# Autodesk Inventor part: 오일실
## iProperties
IsCustomPart: 1
Created: 2009-02
Part Number: 오일실
Material: 고무
Description: 오일-실
Document SubType Name: Modeling
Standard: KS B 2804
Designer: SeoGD™[esajin.kr]
Standards Organization: KS
Language: ko-KR
Size Designation: S - 25 38 8
Categories: <MemberInstance><Categories><Category DisplayName="샤프트 부품" InternalName="7f7aeb1f-a693-4053-b835-cee3144e0d98" Mnemonic="SHFT"><Category DisplayName="실링" Intern
Density: 0.93 g/cm^3
Author: SeoGD™[esajin.kr]
